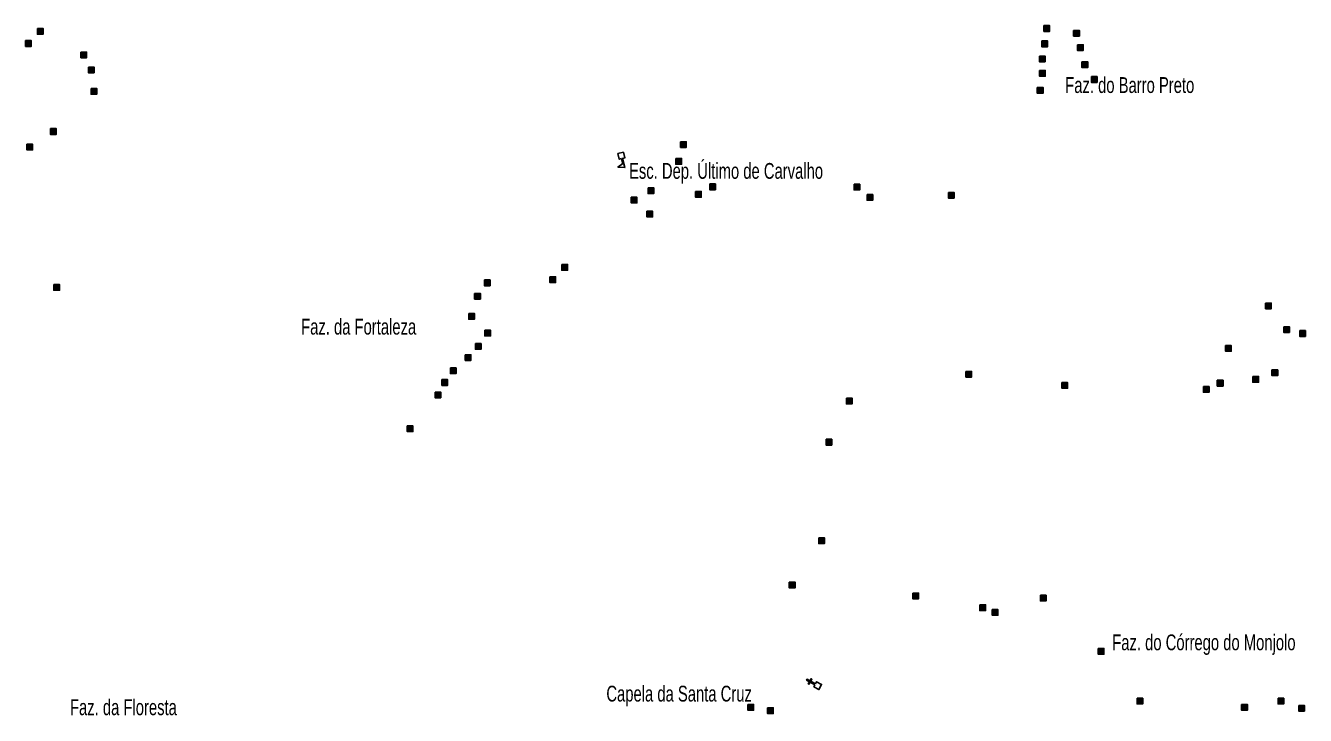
# Model space of a CAD drawing. Extents: x 265.7 to 292.1, y 7676.2 to 7704.2.
# Drawn here: x 279.04 to 285.52, y 7693.56 to 7697.05 of the extents above; entities that cross this region are included whole.
import ezdxf

# ---------------------------------------------------------------- set-up
doc = ezdxf.new("R2010")
doc.units = 0
doc.header["$LTSCALE"] = 0.032
for name, color, linetype, lineweight in [('2', 7, 'Continuous', 25), ('4', 7, 'Continuous', 25), ('6', 7, 'Continuous', 25)]:
    doc.layers.add(name, color=color, linetype=linetype, lineweight=lineweight)
doc.layers.add('61', color=7, linetype='Continuous')

msp = doc.modelspace()

# ---------------------------------------------------------------- hatches: boundary and pattern name
at = {"layer": '2'}
for points in [[(279.0989, 7697.0363), (279.1279, 7697.0363), (279.1279, 7697.0073), (279.0989, 7697.0073)], [(284.1945, 7697.0508), (284.2235, 7697.0508), (284.2235, 7697.0218), (284.1945, 7697.0218)], [(284.3455, 7697.0265), (284.3745, 7697.0265), (284.3745, 7696.9975), (284.3455, 7696.9975)], [(279.0392, 7696.9748), (279.0682, 7696.9748), (279.0682, 7696.9458), (279.0392, 7696.9458)], [(284.1841, 7696.9732), (284.2131, 7696.9732), (284.2131, 7696.9442), (284.1841, 7696.9442)], [(284.3648, 7696.9539), (284.3938, 7696.9539), (284.3938, 7696.9249), (284.3648, 7696.9249)], [(279.3192, 7696.9168), (279.3482, 7696.9168), (279.3482, 7696.8878), (279.3192, 7696.8878)], [(284.172, 7696.8965), (284.201, 7696.8965), (284.201, 7696.8675), (284.172, 7696.8675)], [(284.3875, 7696.8675), (284.4165, 7696.8675), (284.4165, 7696.8385), (284.3875, 7696.8385)], [(279.3571, 7696.8409), (279.3861, 7696.8409), (279.3861, 7696.8119), (279.3571, 7696.8119)], [(284.1728, 7696.8239), (284.2018, 7696.8239), (284.2018, 7696.7949), (284.1728, 7696.7949)], [(279.3708, 7696.7327), (279.3998, 7696.7327), (279.3998, 7696.7037), (279.3708, 7696.7037)], [(284.1614, 7696.7376), (284.1904, 7696.7376), (284.1904, 7696.7086), (284.1614, 7696.7086)], [(284.435, 7696.7925), (284.464, 7696.7925), (284.464, 7696.7635), (284.435, 7696.7635)], [(279.1651, 7696.5294), (279.1941, 7696.5294), (279.1941, 7696.5004), (279.1651, 7696.5004)], [(279.0455, 7696.4503), (279.0745, 7696.4503), (279.0745, 7696.4213), (279.0455, 7696.4213)], [(282.3552, 7696.4632), (282.3842, 7696.4632), (282.3842, 7696.4342), (282.3552, 7696.4342)], [(282.3311, 7696.3785), (282.3601, 7696.3785), (282.3601, 7696.3495), (282.3311, 7696.3495)], [(282.1907, 7696.2299), (282.2197, 7696.2299), (282.2197, 7696.2009), (282.1907, 7696.2009)], [(282.4312, 7696.2115), (282.4602, 7696.2115), (282.4602, 7696.1825), (282.4312, 7696.1825)], [(282.503, 7696.2493), (282.532, 7696.2493), (282.532, 7696.2203), (282.503, 7696.2203)], [(283.2334, 7696.2478), (283.2624, 7696.2478), (283.2624, 7696.2188), (283.2334, 7696.2188)], [(282.1052, 7696.1824), (282.1342, 7696.1824), (282.1342, 7696.1534), (282.1052, 7696.1534)], [(283.2995, 7696.196), (283.3285, 7696.196), (283.3285, 7696.167), (283.2995, 7696.167)], [(283.7111, 7696.2065), (283.7401, 7696.2065), (283.7401, 7696.1775), (283.7111, 7696.1775)], [(282.185, 7696.1114), (282.214, 7696.1114), (282.214, 7696.0824), (282.185, 7696.0824)], [(281.7541, 7695.8418), (281.7831, 7695.8418), (281.7831, 7695.8128), (281.7541, 7695.8128)], [(281.3619, 7695.7634), (281.3909, 7695.7634), (281.3909, 7695.7344), (281.3619, 7695.7344)], [(281.6935, 7695.7795), (281.7225, 7695.7795), (281.7225, 7695.7505), (281.6935, 7695.7505)], [(279.182, 7695.7401), (279.211, 7695.7401), (279.211, 7695.7111), (279.182, 7695.7111)], [(281.3126, 7695.6958), (281.3416, 7695.6958), (281.3416, 7695.6668), (281.3126, 7695.6668)], [(285.3172, 7695.6465), (285.3462, 7695.6465), (285.3462, 7695.6175), (285.3172, 7695.6175)], [(281.2827, 7695.594), (281.3117, 7695.594), (281.3117, 7695.565), (281.2827, 7695.565)], [(281.3642, 7695.5093), (281.3932, 7695.5093), (281.3932, 7695.4803), (281.3642, 7695.4803)], [(285.4092, 7695.527), (285.4382, 7695.527), (285.4382, 7695.498), (285.4092, 7695.498)], [(285.4898, 7695.5069), (285.5188, 7695.5069), (285.5188, 7695.4779), (285.4898, 7695.4779)], [(281.3166, 7695.4415), (281.3456, 7695.4415), (281.3456, 7695.4125), (281.3166, 7695.4125)], [(281.2649, 7695.3849), (281.2939, 7695.3849), (281.2939, 7695.3559), (281.2649, 7695.3559)], [(285.1146, 7695.4318), (285.1436, 7695.4318), (285.1436, 7695.4028), (285.1146, 7695.4028)], [(281.1899, 7695.3187), (281.2189, 7695.3187), (281.2189, 7695.2897), (281.1899, 7695.2897)], [(285.3494, 7695.3083), (285.3784, 7695.3083), (285.3784, 7695.2793), (285.3494, 7695.2793)], [(281.1471, 7695.2591), (281.1761, 7695.2591), (281.1761, 7695.2301), (281.1471, 7695.2301)], [(283.7998, 7695.301), (283.8288, 7695.301), (283.8288, 7695.272), (283.7998, 7695.272)], [(284.2857, 7695.2445), (284.3147, 7695.2445), (284.3147, 7695.2155), (284.2857, 7695.2155)], [(285.0727, 7695.2558), (285.1017, 7695.2558), (285.1017, 7695.2268), (285.0727, 7695.2268)], [(285.2526, 7695.2752), (285.2816, 7695.2752), (285.2816, 7695.2462), (285.2526, 7695.2462)], [(281.1125, 7695.1962), (281.1415, 7695.1962), (281.1415, 7695.1672), (281.1125, 7695.1672)], [(285.0025, 7695.2243), (285.0315, 7695.2243), (285.0315, 7695.1953), (285.0025, 7695.1953)], [(283.1946, 7695.1655), (283.2236, 7695.1655), (283.2236, 7695.1365), (283.1946, 7695.1365)], [(280.9712, 7695.025), (281.0002, 7695.025), (281.0002, 7694.996), (280.9712, 7694.996)], [(283.0921, 7694.9572), (283.1211, 7694.9572), (283.1211, 7694.9282), (283.0921, 7694.9282)], [(283.055, 7694.4585), (283.084, 7694.4585), (283.084, 7694.4295), (283.055, 7694.4295)], [(282.9057, 7694.2341), (282.9347, 7694.2341), (282.9347, 7694.2051), (282.9057, 7694.2051)], [(283.5311, 7694.1792), (283.5601, 7694.1792), (283.5601, 7694.1502), (283.5311, 7694.1502)], [(284.1768, 7694.168), (284.2058, 7694.168), (284.2058, 7694.139), (284.1768, 7694.139)], [(283.8702, 7694.1195), (283.8992, 7694.1195), (283.8992, 7694.0905), (283.8702, 7694.0905)], [(283.933, 7694.0954), (283.962, 7694.0954), (283.962, 7694.0664), (283.933, 7694.0664)], [(284.4698, 7693.8984), (284.4988, 7693.8984), (284.4988, 7693.8694), (284.4698, 7693.8694)], [(284.6666, 7693.6466), (284.6956, 7693.6466), (284.6956, 7693.6176), (284.6666, 7693.6176)], [(285.3801, 7693.6466), (285.4091, 7693.6466), (285.4091, 7693.6176), (285.3801, 7693.6176)], [(282.6959, 7693.6151), (282.7249, 7693.6151), (282.7249, 7693.5861), (282.6959, 7693.5861)], [(282.7959, 7693.5982), (282.8249, 7693.5982), (282.8249, 7693.5692), (282.7959, 7693.5692)], [(285.1961, 7693.6151), (285.2251, 7693.6151), (285.2251, 7693.5861), (285.1961, 7693.5861)], [(285.485, 7693.6102), (285.514, 7693.6102), (285.514, 7693.5812), (285.485, 7693.5812)]]:
    msp.add_hatch(color=256, dxfattribs=at).paths.add_polyline_path(points)

# ---------------------------------------------------------------- linework, layer by layer
for points in [[(279.0989, 7697.0363), (279.1279, 7697.0363), (279.1279, 7697.0073), (279.0989, 7697.0073)], [(284.1945, 7697.0508), (284.2235, 7697.0508), (284.2235, 7697.0218), (284.1945, 7697.0218)], [(284.3455, 7697.0265), (284.3745, 7697.0265), (284.3745, 7696.9975), (284.3455, 7696.9975)], [(279.0392, 7696.9748), (279.0682, 7696.9748), (279.0682, 7696.9458), (279.0392, 7696.9458)], [(284.1841, 7696.9732), (284.2131, 7696.9732), (284.2131, 7696.9442), (284.1841, 7696.9442)], [(284.3648, 7696.9539), (284.3938, 7696.9539), (284.3938, 7696.9249), (284.3648, 7696.9249)], [(279.3192, 7696.9168), (279.3482, 7696.9168), (279.3482, 7696.8878), (279.3192, 7696.8878)], [(284.172, 7696.8965), (284.201, 7696.8965), (284.201, 7696.8675), (284.172, 7696.8675)], [(284.3875, 7696.8675), (284.4165, 7696.8675), (284.4165, 7696.8385), (284.3875, 7696.8385)], [(279.3571, 7696.8409), (279.3861, 7696.8409), (279.3861, 7696.8119), (279.3571, 7696.8119)], [(284.1728, 7696.8239), (284.2018, 7696.8239), (284.2018, 7696.7949), (284.1728, 7696.7949)], [(279.3708, 7696.7327), (279.3998, 7696.7327), (279.3998, 7696.7037), (279.3708, 7696.7037)], [(284.1614, 7696.7376), (284.1904, 7696.7376), (284.1904, 7696.7086), (284.1614, 7696.7086)], [(284.435, 7696.7925), (284.464, 7696.7925), (284.464, 7696.7635), (284.435, 7696.7635)], [(279.1651, 7696.5294), (279.1941, 7696.5294), (279.1941, 7696.5004), (279.1651, 7696.5004)], [(279.0455, 7696.4503), (279.0745, 7696.4503), (279.0745, 7696.4213), (279.0455, 7696.4213)], [(282.3552, 7696.4632), (282.3842, 7696.4632), (282.3842, 7696.4342), (282.3552, 7696.4342)], [(282.3311, 7696.3785), (282.3601, 7696.3785), (282.3601, 7696.3495), (282.3311, 7696.3495)], [(282.1907, 7696.2299), (282.2197, 7696.2299), (282.2197, 7696.2009), (282.1907, 7696.2009)], [(282.4312, 7696.2115), (282.4602, 7696.2115), (282.4602, 7696.1825), (282.4312, 7696.1825)], [(282.503, 7696.2493), (282.532, 7696.2493), (282.532, 7696.2203), (282.503, 7696.2203)], [(283.2334, 7696.2478), (283.2624, 7696.2478), (283.2624, 7696.2188), (283.2334, 7696.2188)], [(282.1052, 7696.1824), (282.1342, 7696.1824), (282.1342, 7696.1534), (282.1052, 7696.1534)], [(283.2995, 7696.196), (283.3285, 7696.196), (283.3285, 7696.167), (283.2995, 7696.167)], [(283.7111, 7696.2065), (283.7401, 7696.2065), (283.7401, 7696.1775), (283.7111, 7696.1775)], [(282.185, 7696.1114), (282.214, 7696.1114), (282.214, 7696.0824), (282.185, 7696.0824)], [(281.7541, 7695.8418), (281.7831, 7695.8418), (281.7831, 7695.8128), (281.7541, 7695.8128)], [(281.3619, 7695.7634), (281.3909, 7695.7634), (281.3909, 7695.7344), (281.3619, 7695.7344)], [(281.6935, 7695.7795), (281.7225, 7695.7795), (281.7225, 7695.7505), (281.6935, 7695.7505)], [(279.182, 7695.7401), (279.211, 7695.7401), (279.211, 7695.7111), (279.182, 7695.7111)], [(281.3126, 7695.6958), (281.3416, 7695.6958), (281.3416, 7695.6668), (281.3126, 7695.6668)], [(285.3172, 7695.6465), (285.3462, 7695.6465), (285.3462, 7695.6175), (285.3172, 7695.6175)], [(281.2827, 7695.594), (281.3117, 7695.594), (281.3117, 7695.565), (281.2827, 7695.565)], [(281.3642, 7695.5093), (281.3932, 7695.5093), (281.3932, 7695.4803), (281.3642, 7695.4803)], [(285.4092, 7695.527), (285.4382, 7695.527), (285.4382, 7695.498), (285.4092, 7695.498)], [(285.4898, 7695.5069), (285.5188, 7695.5069), (285.5188, 7695.4779), (285.4898, 7695.4779)], [(281.3166, 7695.4415), (281.3456, 7695.4415), (281.3456, 7695.4125), (281.3166, 7695.4125)], [(281.2649, 7695.3849), (281.2939, 7695.3849), (281.2939, 7695.3559), (281.2649, 7695.3559)], [(285.1146, 7695.4318), (285.1436, 7695.4318), (285.1436, 7695.4028), (285.1146, 7695.4028)], [(281.1899, 7695.3187), (281.2189, 7695.3187), (281.2189, 7695.2897), (281.1899, 7695.2897)], [(285.3494, 7695.3083), (285.3784, 7695.3083), (285.3784, 7695.2793), (285.3494, 7695.2793)], [(281.1471, 7695.2591), (281.1761, 7695.2591), (281.1761, 7695.2301), (281.1471, 7695.2301)], [(283.7998, 7695.301), (283.8288, 7695.301), (283.8288, 7695.272), (283.7998, 7695.272)], [(284.2857, 7695.2445), (284.3147, 7695.2445), (284.3147, 7695.2155), (284.2857, 7695.2155)], [(285.0727, 7695.2558), (285.1017, 7695.2558), (285.1017, 7695.2268), (285.0727, 7695.2268)], [(285.2526, 7695.2752), (285.2816, 7695.2752), (285.2816, 7695.2462), (285.2526, 7695.2462)], [(281.1125, 7695.1962), (281.1415, 7695.1962), (281.1415, 7695.1672), (281.1125, 7695.1672)], [(285.0025, 7695.2243), (285.0315, 7695.2243), (285.0315, 7695.1953), (285.0025, 7695.1953)], [(283.1946, 7695.1655), (283.2236, 7695.1655), (283.2236, 7695.1365), (283.1946, 7695.1365)], [(280.9712, 7695.025), (281.0002, 7695.025), (281.0002, 7694.996), (280.9712, 7694.996)], [(283.0921, 7694.9572), (283.1211, 7694.9572), (283.1211, 7694.9282), (283.0921, 7694.9282)], [(283.055, 7694.4585), (283.084, 7694.4585), (283.084, 7694.4295), (283.055, 7694.4295)], [(282.9057, 7694.2341), (282.9347, 7694.2341), (282.9347, 7694.2051), (282.9057, 7694.2051)], [(283.5311, 7694.1792), (283.5601, 7694.1792), (283.5601, 7694.1502), (283.5311, 7694.1502)], [(284.1768, 7694.168), (284.2058, 7694.168), (284.2058, 7694.139), (284.1768, 7694.139)], [(283.8702, 7694.1195), (283.8992, 7694.1195), (283.8992, 7694.0905), (283.8702, 7694.0905)], [(283.933, 7694.0954), (283.962, 7694.0954), (283.962, 7694.0664), (283.933, 7694.0664)], [(284.4698, 7693.8984), (284.4988, 7693.8984), (284.4988, 7693.8694), (284.4698, 7693.8694)], [(284.6666, 7693.6466), (284.6956, 7693.6466), (284.6956, 7693.6176), (284.6666, 7693.6176)], [(285.3801, 7693.6466), (285.4091, 7693.6466), (285.4091, 7693.6176), (285.3801, 7693.6176)], [(282.6959, 7693.6151), (282.7249, 7693.6151), (282.7249, 7693.5861), (282.6959, 7693.5861)], [(282.7959, 7693.5982), (282.8249, 7693.5982), (282.8249, 7693.5692), (282.7959, 7693.5692)], [(285.1961, 7693.6151), (285.2251, 7693.6151), (285.2251, 7693.5861), (285.1961, 7693.5861)], [(285.485, 7693.6102), (285.514, 7693.6102), (285.514, 7693.5812), (285.485, 7693.5812)]]:
    msp.add_lwpolyline(points, close=True, dxfattribs=at)
at = {"layer": '4'}
for points in [[(282.0569, 7696.3778), (282.0451, 7696.3748), (282.038, 7696.4029), (282.0661, 7696.41), (282.0732, 7696.3819), (282.0616, 7696.379)], [(282.0616, 7696.379), (282.0736, 7696.3321), (282.0378, 7696.3349), (282.0633, 7696.3525), (282.0569, 7696.3778)]]:
    msp.add_lwpolyline(points, dxfattribs=at)
at = {"layer": '6'}
for points in [[(283.0359, 7693.7152), (283.012, 7693.7281), (283.0062, 7693.7174), (283.002, 7693.7197), (283.0077, 7693.7304), (282.9932, 7693.7382), (282.9956, 7693.7424), (283.01, 7693.7347), (283.0157, 7693.7453), (283.0201, 7693.7429), (283.0143, 7693.7323), (283.0381, 7693.7194)], [(283.0381, 7693.7194), (283.0439, 7693.7301), (283.0694, 7693.7163), (283.0556, 7693.6908), (283.0301, 7693.7045), (283.0359, 7693.7152)]]:
    msp.add_lwpolyline(points, dxfattribs=at)

# ---------------------------------------------------------------- texts
at = {"layer": '61', "width": 0.7}
for s, p in [('Faz. do Barro Preto', (284.3028, 7696.7099)), ('Esc. Dep. Último de Carvalho', (282.0944, 7696.2755)), ('Faz. da Fortaleza', (280.4341, 7695.4871)), ('Faz. do Córrego do Monjolo', (284.5408, 7693.8895)), ('Capela da Santa Cruz', (281.9796, 7693.6299)), ('Faz. da Floresta', (279.264, 7693.5609))]:
    msp.add_text(s, height=0.08, dxfattribs=at).set_placement(p)

doc.saveas('drawing.dxf')
